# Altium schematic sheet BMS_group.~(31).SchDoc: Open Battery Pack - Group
size A3; Author: Morgane Vallée; Revision: 1.0; SheetNumber: 2; SheetTotal: 3
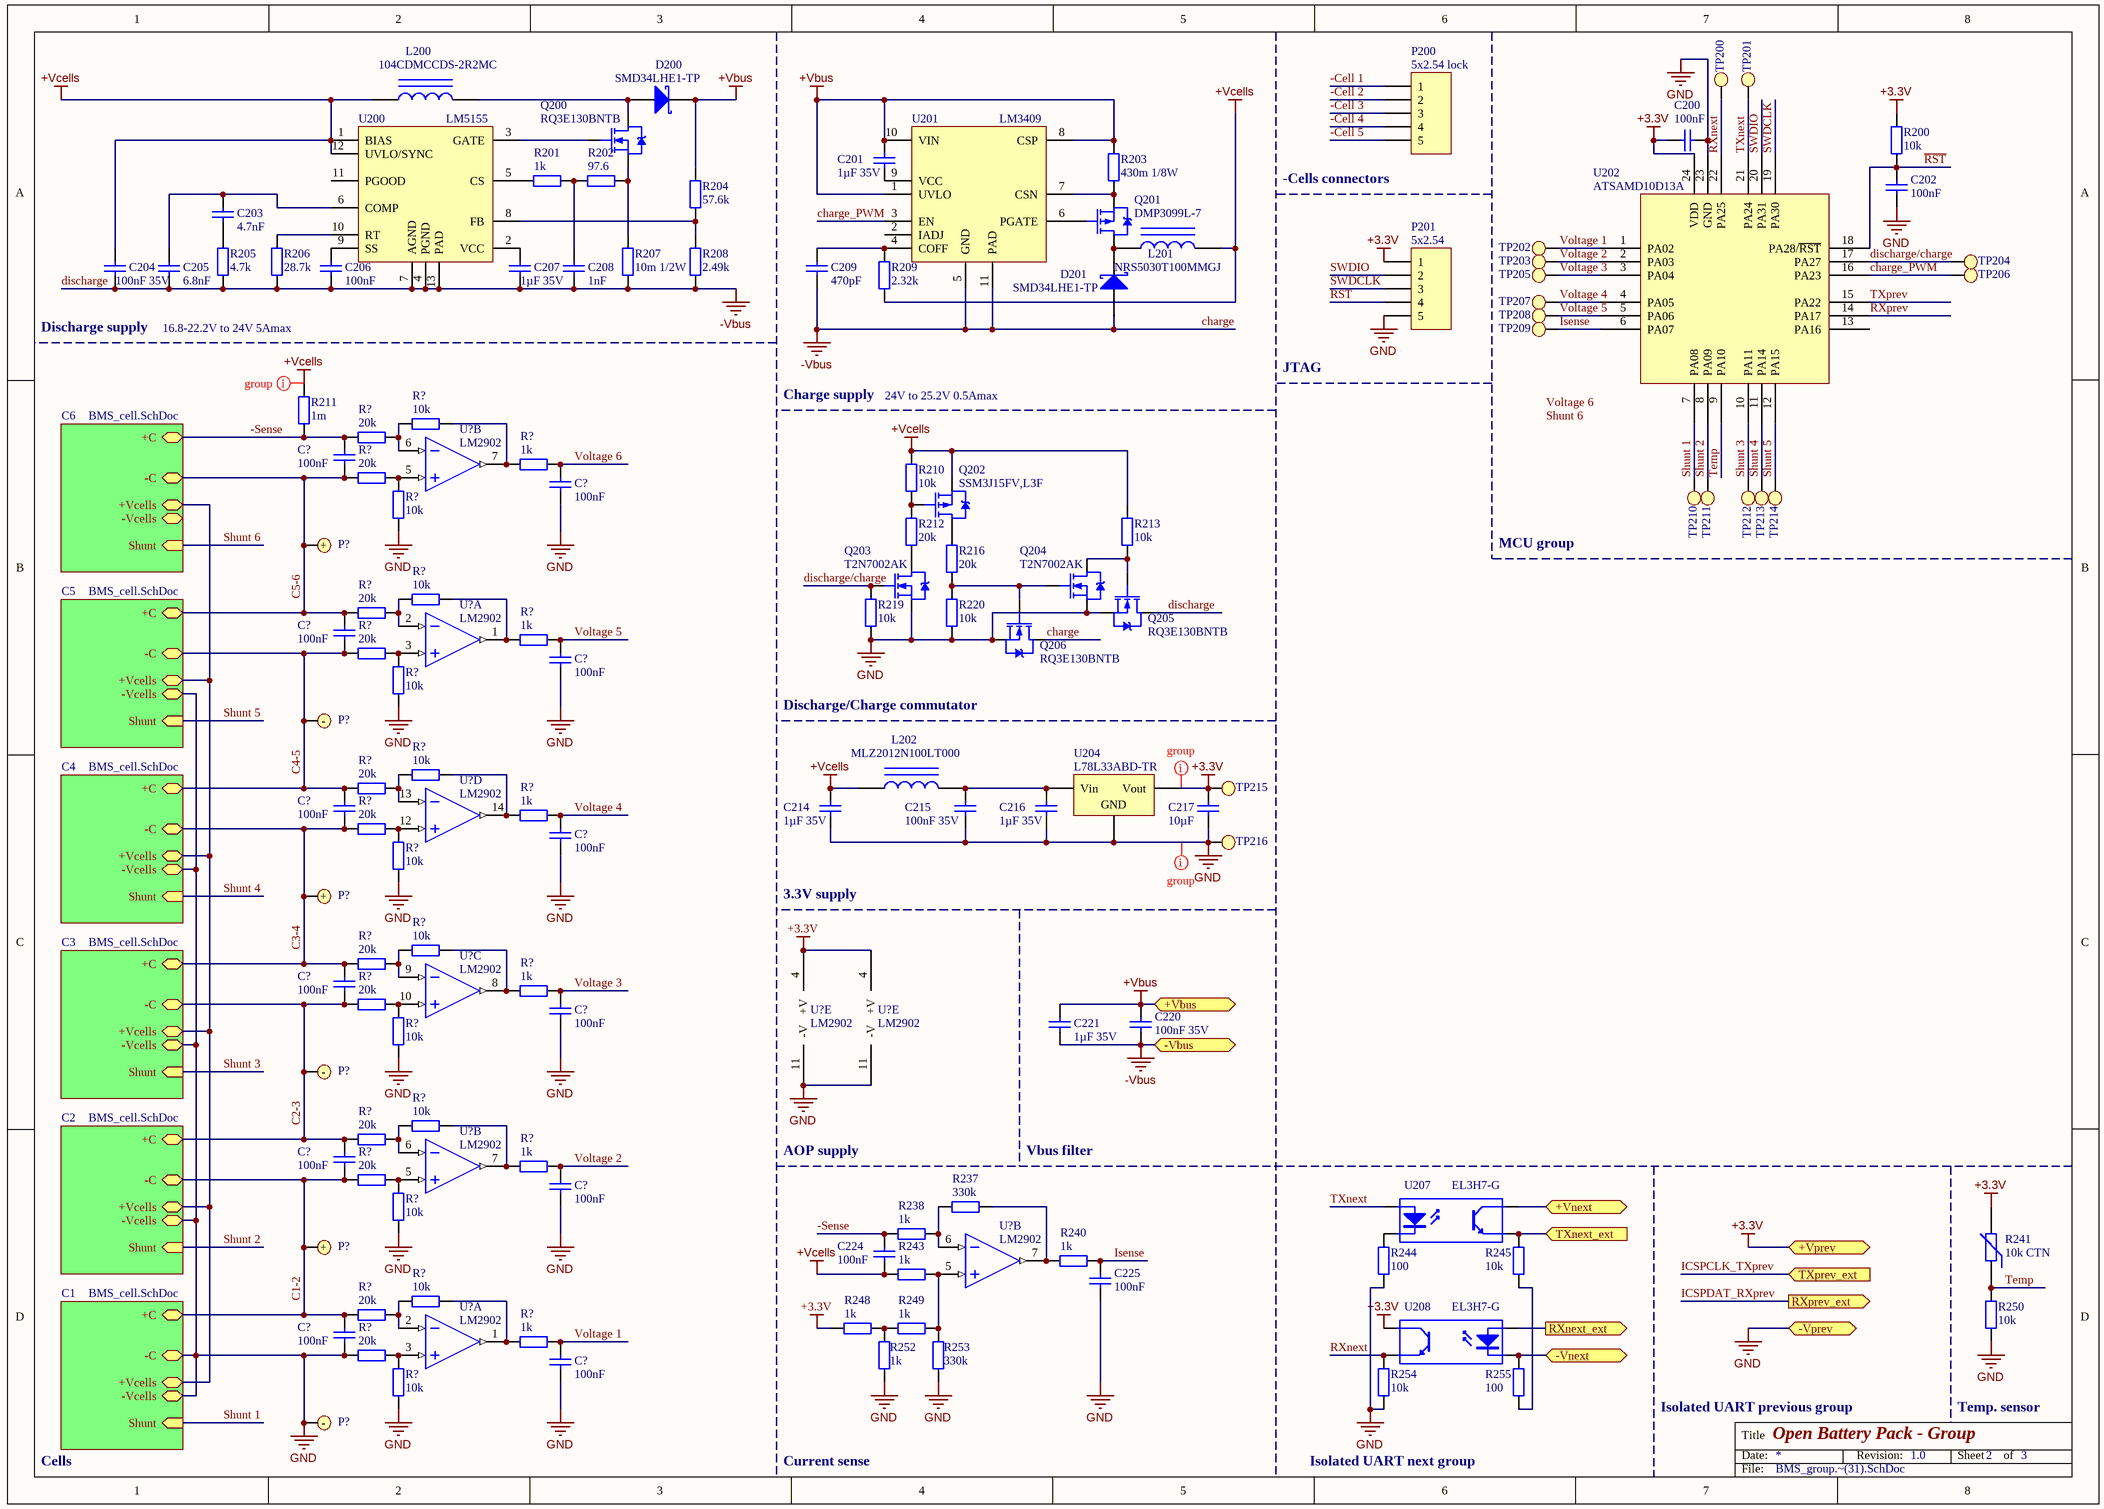
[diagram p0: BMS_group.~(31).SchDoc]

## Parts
(Parts that share a designator on the sheet are numbered #1, #2 ... from top to bottom, then left to right.)
C200  100nF  [C0603]
C201  1µF 35V  [C0805]
C202  100nF  [C0603]
C203  4.7nF  [C0603]
C204  100nF 35V  [C0603]
C205  6.8nF  [C0603]
C206  100nF  [C0603]
C207  1µF 35V  [C0805]
C208  1nF  [C0603]
C209  470pF  [C0603]
C214  1µF 35V  [C0805]
C215  100nF 35V  [C0603]
C216  1µF 35V  [C0805]
C217  10µF  [C0603]
C220  100nF 35V  [C0603]
C221  1µF 35V  [C0805]
C224  100nF  [C0603]
C225  100nF  [C0603]
C?#1  100nF  [C0603]
C?#2  100nF  [C0603]
C?#3  100nF  [C0603]
C?#4  100nF  [C0603]
C?#5  100nF  [C0603]
C?#6  100nF  [C0603]
C?#7  100nF  [C0603]
C?#8  100nF  [C0603]
C?#9  100nF  [C0603]
C?#10  100nF  [C0603]
C?#11  100nF  [C0603]
C?#12  100nF  [C0603]
D200  SMD34LHE1-TP  [SOD-123H]
D201  SMD34LHE1-TP  [SOD-123H]
L200  104CDMCCDS-2R2MC  [SELF_SMD_8x8]
L201  NRS5030T100MMGJ  [SELF_SMD_4.9x4.9]
L202  MLZ2012N100LT000  [FER 0805/2012]
P200  5x2.54 lock  [MOLEX KK 0022272051]
P201  5x2.54  [HDR1X5]
P?#1  Bat+  [Keystone 241]  (value not drawn)
P?#2  Bat-  [Keystone 2993]  (value not drawn)
P?#3  Bat+  [Keystone 241]  (value not drawn)
P?#4  Bat-  [Keystone 2993]  (value not drawn)
P?#5  Bat+  [Keystone 241]  (value not drawn)
P?#6  Bat-  [Keystone 2993]  (value not drawn)
Q200  RQ3E130BNTB  [INFINEON PG-TSDSON-8]
Q201  DMP3099L-7  [DIODES SOT-23-3]
Q202  SSM3J15FV,L3F  [DIODES SOT-23-3]
Q203  T2N7002AK  [DIODES SOT-23-3]
Q204  T2N7002AK  [DIODES SOT-23-3]
Q205  RQ3E130BNTB  [INFINEON PG-TSDSON-8]
Q206  RQ3E130BNTB  [INFINEON PG-TSDSON-8]
R200  10k  [R0603]
R201  1k  [R0603]
R202  97.6  [R0603]
R203  430m 1/8W  [R0603]
R204  57.6k  [R0603]
R205  4.7k  [R0603]
R206  28.7k  [R0603]
R207  10m 1/2W  [R1206]
R208  2.49k  [R0603]
R209  2.32k  [R0603]
R210  10k  [R0603]
R211  1m  [R1206]
R212  20k  [R0603]
R213  10k  [R0603]
R216  20k  [R0603]
R219  10k  [R0603]
R220  10k  [R0603]
R237  330k  [R0603]
R238  1k  [R0603]
R240  1k  [R0603]
R241  10k CTN  [NTC 0402/1005]
R243  1k  [R0603]
R244  100  [R0603]
R245  10k  [R0603]
R248  1k  [R0603]
R249  1k  [R0603]
R250  10k  [R0603]
R252  1k  [R0603]
R253  330k  [R0603]
R254  10k  [R0603]
R255  100  [R0603]
R?#1  10k  [R0603]
R?#2  20k  [R0603]
R?#3  1k  [R0603]
R?#4  20k  [R0603]
R?#5  10k  [R0603]
R?#6  10k  [R0603]
R?#7  20k  [R0603]
R?#8  1k  [R0603]
R?#9  20k  [R0603]
R?#10  10k  [R0603]
R?#11  10k  [R0603]
R?#12  20k  [R0603]
R?#13  1k  [R0603]
R?#14  20k  [R0603]
R?#15  10k  [R0603]
R?#16  10k  [R0603]
R?#17  20k  [R0603]
R?#18  1k  [R0603]
R?#19  20k  [R0603]
R?#20  10k  [R0603]
R?#21  10k  [R0603]
R?#22  20k  [R0603]
R?#23  1k  [R0603]
R?#24  20k  [R0603]
R?#25  10k  [R0603]
R?#26  10k  [R0603]
R?#27  20k  [R0603]
R?#28  1k  [R0603]
R?#29  20k  [R0603]
R?#30  10k  [R0603]
TP200  Test Point  [Test Point]  (value not drawn)
TP201  Test Point  [Test Point]  (value not drawn)
TP202  Test Point  [Test Point]  (value not drawn)
TP203  Test Point  [Test Point]  (value not drawn)
TP204  Test Point  [Test Point]  (value not drawn)
TP205  Test Point  [Test Point]  (value not drawn)
TP206  Test Point  [Test Point]  (value not drawn)
TP207  Test Point  [Test Point]  (value not drawn)
TP208  Test Point  [Test Point]  (value not drawn)
TP209  Test Point  [Test Point]  (value not drawn)
TP210  Test Point  [Test Point]  (value not drawn)
TP211  Test Point  [Test Point]  (value not drawn)
TP212  Test Point  [Test Point]  (value not drawn)
TP213  Test Point  [Test Point]  (value not drawn)
TP214  Test Point  [Test Point]  (value not drawn)
TP215  Test Point  [Test Point]  (value not drawn)
TP216  Test Point  [Test Point]  (value not drawn)
U200  LM5155  [TI WSON-12]
U201  LM3409  [TI MSOP-10 DGQ]
U202  ATSAMD10D13A  [SMSC QFN-24 4x4MM]
U204  L78L33ABD-TR  [ST SOIC-8N]
U207  EL3H7-G  [OPTO_EL3H7-G]
U208  EL3H7-G  [OPTO_EL3H7-G]
U?#1  LM2902  [Atmel SO-14 14S1]  (part B of 5)
U?#2  LM2902  [Atmel SO-14 14S1]  (part A of 5)
U?#3  LM2902  [Atmel SO-14 14S1]  (part D of 5)
U?#4  LM2902  [Atmel SO-14 14S1]  (part C of 5)
U?#5  LM2902  [Atmel SO-14 14S1]  (part E of 5)
U?#6  LM2902  [Atmel SO-14 14S1]  (part E of 5)
U?#7  LM2902  [Atmel SO-14 14S1]  (part B of 5)
U?#8  LM2902  [Atmel SO-14 14S1]  (part B of 5)
U?#9  LM2902  [Atmel SO-14 14S1]  (part A of 5)

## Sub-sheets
C1 = BMS_cell.SchDoc: -C, +C, +Vcells, -Vcells, Shunt (in)
C2 = BMS_cell.SchDoc: -C, +C, +Vcells, -Vcells, Shunt (in)
C3 = BMS_cell.SchDoc: -C, +C, +Vcells, -Vcells, Shunt (in)
C4 = BMS_cell.SchDoc: -C, +C, +Vcells, -Vcells, Shunt (in)
C5 = BMS_cell.SchDoc: -C, +C, +Vcells, -Vcells, Shunt (in)
C6 = BMS_cell.SchDoc: -C, +C, +Vcells, -Vcells, Shunt (in)

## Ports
+Vbus, +Vnext, +Vprev, -Vbus, -Vnext, -Vprev, RXnext_ext (out), RXprev_ext (out), TXnext_ext (in), TXprev_ext (in)

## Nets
+3.3V: C200.2 C217.1 P201.1 R200.2 R241.2 R248.2 TP215.1 U202.24(VDD) U204.3(Vout) U208.4(C) U?#5.4(+V) U?#6.4(+V) ; port +Vprev
+Vbus: C201.1 C220.1 C221.1 D200.3(K) R203.2 R204.2 U201.1(UVLO) U201.8(CSP) U201.10(VIN) ; port +Vbus
+Vcells: C204.1 C214.1 C224.2 L200.1 L201.2 L202.1 Q202.2(S) R209.2 R210.2 R211.2 R213.2 R243.2 U200.1(BIAS) U200.12(UVLO/SYNC)
charge: C204.2 C205.2 C206.2 C207.2 C208.2 C209.2 C220.2 C221.2 D201.1(A) Q205.3(D) Q206.3(D) R205.1 R206.1 R207.1 R208.1 U200.4(PGND) U200.7(AGND) U200.13(PAD) U201.5(GND) U201.11(PAD) ; port -Vbus  [also labelled -Vbus, discharge]
GND: C200.1 C202.1 C214.2 C215.2 C216.2 C217.2 C225.2 C?#2.2 C?#4.2 C?#6.2 C?#8.2 C?#10.2 C?#11.2 C?#12.2 P201.5 P?#6.1 Q203.2(S) Q204.2(S) Q205.2(S) Q206.2(S) R219.1 R220.1 R244.1 R250.2 R252.2 R253.1 R254.1 R?#5.2 R?#10.2 R?#15.2 R?#20.2 R?#25.2 R?#29.2 R?#30.2 TP216.1 U202.23(GND) U204.2(GND) U?#5.11(-V) U?#6.11(-V) ; port -Vprev, sheet C1/-C, sheet C1/-Vcells, sheet C2/-Vcells, sheet C3/-Vcells, sheet C4/-Vcells, sheet C5/-Vcells
+Vnext: U207.4(C) ; port +Vnext
-Cell 1: P200.1
-Cell 2: P200.2
-Cell 3: P200.3
-Cell 4: P200.4
-Cell 5: P200.5
-Sense: C224.1 C?#1.1 R211.1 R238.1 R?#2.1 ; sheet C6/+C
-Vnext: R255.1 U208.2(K) ; port -Vnext
C1-2: C?#9.2 C?#11.1 P?#5.1 R?#24.2 R?#27.1 ; sheet C1/+C, sheet C2/-C
C2-3: C?#7.2 C?#9.1 P?#4.1 R?#19.2 R?#22.1 ; sheet C2/+C, sheet C3/-C
C3-4: C?#5.2 C?#7.1 P?#3.1 R?#14.2 R?#17.1 ; sheet C3/+C, sheet C4/-C
C4-5: C?#3.2 C?#5.1 P?#2.1 R?#9.2 R?#12.1 ; sheet C4/+C, sheet C5/-C
C5-6: C?#1.2 C?#3.1 P?#1.1 R?#4.2 R?#7.1 ; sheet C5/+C, sheet C6/-C
charge_PWM: TP206.1 U201.3(EN) U202.16(PA23)
discharge/charge: Q203.1(G) R219.2 TP204.1 U202.17(PA27)
Isense: C225.1 R240.1 TP209.1 U202.6(PA07)
~{RST}: C202.2 P201.4 R200.1 U202.18(PA28/~{RST})
RXnext: R254.2 TP200.1 U202.22(PA25) U208.3(E)
RXnext_ext: U208.1(A) ; port RXnext_ext
RXprev: U202.14(PA17)
Shunt 1: TP210.1 U202.7(PA08) ; sheet C1/Shunt
Shunt 2: TP211.1 U202.8(PA09) ; sheet C2/Shunt
Shunt 3: TP212.1 U202.10(PA11) ; sheet C3/Shunt
Shunt 4: TP213.1 U202.11(PA14) ; sheet C4/Shunt
Shunt 5: TP214.1 U202.12(PA15) ; sheet C5/Shunt
SWDCLK: P201.3 U202.19(PA30)
SWDIO: P201.2 U202.20(PA31)
Temp: R241.1 R250.1 U202.9(PA10)
TXnext: TP201.1 U202.21(PA24) U207.1(A)
TXnext_ext: R245.1 U207.3(E) ; port TXnext_ext
TXprev: U202.15(PA22)
Voltage 1: C?#12.1 R?#28.1 TP202.1 U202.1(PA02)
Voltage 2: C?#10.1 R?#23.1 TP203.1 U202.2(PA03)
Voltage 3: C?#8.1 R?#18.1 TP205.1 U202.3(PA04)
Voltage 4: C?#6.1 R?#13.1 TP207.1 U202.4(PA05)
Voltage 5: C?#4.1 R?#8.1 TP208.1 U202.5(PA06)
Voltage 6: C?#2.1 R?#3.1
NetC201_2: C201.2 U201.9(VCC)
NetC203_1: C203.1 C205.1 U200.6(COMP)
NetC203_2: C203.2 R205.2
NetC206_1: C206.1 U200.9(SS)
NetC207_1: C207.1 U200.2(VCC)
NetC208_1: C208.1 R201.1 R202.2
NetC209_1: C209.1 R209.1 U201.4(COFF)
NetC215_1: C215.1 C216.1 L202.2 U204.1(Vin)
NetD200_1: D200.1(A) L200.2 Q200.3(D)
NetD201_3: D201.3(K) L201.1 Q201.3(D)
NetQ200_1: Q200.1(G) U200.3(GATE)
NetQ200_2: Q200.2(S) R202.1 R207.2
NetQ201_1: Q201.1(G) U201.6(PGATE)
NetQ201_2: Q201.2(S) R203.1 U201.7(CSN)
NetQ202_1: Q202.1(G) R210.1 R212.2
NetQ202_3: Q202.3(D) R216.2
NetQ203_3: Q203.3(D) R212.1
NetQ204_1: Q204.1(G) Q206.1(G) R216.1 R220.2
NetQ204_3: Q204.3(D) Q205.1(G) R213.1
NetR201_2: R201.2 U200.5(CS)
NetR204_1: R204.1 R208.2 U200.8(FB)
NetR206_2: R206.2 U200.10(RT)
NetR237_1: R237.1 R240.2 U?#8.7(OUT)
NetR237_2: R237.2 R238.2 U?#8.6(IN-)
NetR243_1: R243.1 R249.1 R253.2 U?#8.5(IN+)
NetR244_2: R244.2 U207.2(K)
NetR245_2: R245.2 R255.2
NetR248_1: R248.1 R249.2 R252.1
NetR?#1_1: R?#1.1 R?#2.2 U?#1.6(IN-)
NetR?#1_2: R?#1.2 R?#3.2 U?#1.7(OUT)
NetR?#4_1: R?#4.1 R?#5.1 U?#1.5(IN+)
NetR?#6_1: R?#6.1 R?#7.2 U?#2.2(IN-)
NetR?#6_2: R?#6.2 R?#8.2 U?#2.1(OUT)
NetR?#9_1: R?#9.1 R?#10.1 U?#2.3(IN+)
NetR?#11_1: R?#11.1 R?#12.2 U?#3.13(IN-)
NetR?#11_2: R?#11.2 R?#13.2 U?#3.14(OUT)
NetR?#14_1: R?#14.1 R?#15.1 U?#3.12(IN+)
NetR?#16_1: R?#16.1 R?#17.2 U?#4.9(IN-)
NetR?#16_2: R?#16.2 R?#18.2 U?#4.8(OUT)
NetR?#19_1: R?#19.1 R?#20.1 U?#4.10(IN+)
NetR?#21_1: R?#21.1 R?#22.2 U?#7.6(IN-)
NetR?#21_2: R?#21.2 R?#23.2 U?#7.7(OUT)
NetR?#24_1: R?#24.1 R?#25.1 U?#7.5(IN+)
NetR?#26_1: R?#26.1 R?#27.2 U?#9.2(IN-)
NetR?#26_2: R?#26.2 R?#28.2 U?#9.1(OUT)
NetR?#29_1: R?#29.1 R?#30.1 U?#9.3(IN+)
(unnamed): sheet C1/+Vcells, sheet C2/+Vcells, sheet C3/+Vcells, sheet C4/+Vcells, sheet C5/+Vcells, sheet C6/+Vcells

Not connected (* = marked no-connect by the designer): U200 11(PGOOD); U201 2(IADJ); U202 13(PA16)

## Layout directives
net class Group: +3.3V, +Vcells, GND

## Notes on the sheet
- (near P200) -Cells connectors
- Discharge supply
- 16.8-22.2V to 24V 5Amax
- JTAG
- Charge supply
- 24V to 25.2V 0.5Amax
- MCU group
- Discharge/Charge commutator
- 3.3V supply
- AOP supply
- Vbus filter
- Isolated UART previous group
- Temp. sensor
- Cells
- Current sense
- Isolated UART next group
- Labels drawn without touching a wire or pin: Shunt 6, Voltage 6

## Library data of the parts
C200-C209 C214-C217 C220 C221 C224 C225 C?#1-C?#12 = Cap: Capacitor
D200 D201 = Diode BAT17
L200-L202 = Inductor Iron: Magnetic-Core Inductor
P200 P201 = Header 5: Header, 5-Pin
P?#1 P?#3 P?#5 = Bat+: Battery contact +
P?#2 P?#4 P?#6 = Bat-: Battery contact -
Q200 Q203-Q206 = MOSFET_N
Q201 Q202 = MOSFET_P
R200-R213 R216 R219 R220 R237 R238 R240 R243-R245 R248-R250 R252-R255 R?#1-R?#30 = Res2: Resistor
R241 = Res Varistor: Varistor (Voltage-Sensitive Resistor)
U200 = LM5155: 2.2-MHz Wide Input Nonsynchronous Boost, SEPIC, Flyback Controller
U201 = LM3409: P-FET Buck Controller for High-Power LED Drivers
U204 = Volt Reg: Voltage Regulator; pin to pad: 1>8 2>2+3+6+7 3>1
U207 U208 = Optoisolator1: 4-Pin Phototransistor Optocoupler
U?#1-U?#9 = LM2902: Low-power quad operational amplifiers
